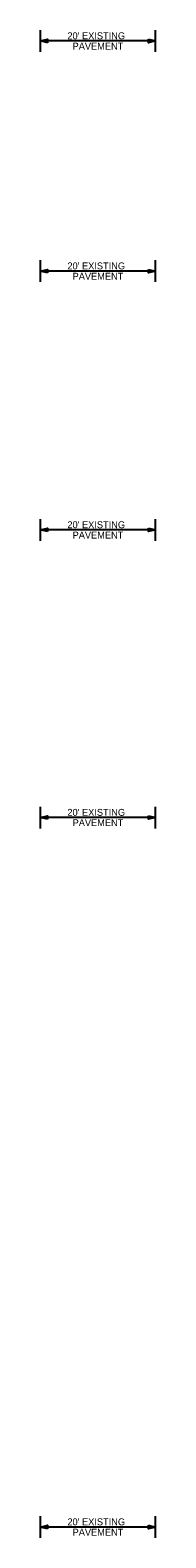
# Model space of a CAD drawing. Extents: x 1368713 to 1370673, y 380279 to 380950.
# Drawn here: x 1368712.9 to 1368732.9, y 380427.5 to 380689.6 of the extents above; entities that cross this region are included whole.
import ezdxf

# ---------------------------------------------------------------- set-up
doc = ezdxf.new("R2010")
doc.units = 0
doc.layers.add('R_ROW Annot', color=7, linetype='Continuous')

msp = doc.modelspace()

# ---------------------------------------------------------------- linework, layer by layer
at = {"layer": 'R_ROW Annot'}
for p, q in [((1368712.9, 380685.87), (1368712.9, 380689.64)), ((1368732.9, 380685.87), (1368732.9, 380689.64)), ((1368732.9, 380687.76), (1368712.9, 380687.76)), ((1368712.9, 380645.87), (1368712.9, 380649.64)), ((1368732.9, 380645.87), (1368732.9, 380649.64)), ((1368732.9, 380647.76), (1368712.9, 380647.76)), ((1368712.9, 380600.87), (1368712.9, 380604.64)), ((1368732.9, 380602.76), (1368712.9, 380602.76)), ((1368732.9, 380600.87), (1368732.9, 380604.64)), ((1368712.9, 380550.87), (1368712.9, 380554.64)), ((1368732.9, 380552.76), (1368712.9, 380552.76)), ((1368732.9, 380550.87), (1368732.9, 380554.64)), ((1368712.9, 380427.54), (1368712.9, 380431.3)), ((1368732.9, 380429.42), (1368712.9, 380429.42)), ((1368732.9, 380427.54), (1368732.9, 380431.3))]:
    msp.add_line(p, q, dxfattribs=at)
for points in [[(1368714.1, 380687.46), (1368712.9, 380687.76), (1368714.1, 380688.06)], [(1368731.7, 380688.06), (1368732.9, 380687.76), (1368731.7, 380687.46)], [(1368714.1, 380647.46), (1368712.9, 380647.76), (1368714.1, 380648.06)], [(1368731.7, 380648.06), (1368732.9, 380647.76), (1368731.7, 380647.46)], [(1368714.1, 380602.46), (1368712.9, 380602.76), (1368714.1, 380603.06)], [(1368731.7, 380603.06), (1368732.9, 380602.76), (1368731.7, 380602.46)], [(1368714.1, 380552.46), (1368712.9, 380552.76), (1368714.1, 380553.06)], [(1368731.7, 380553.06), (1368732.9, 380552.76), (1368731.7, 380552.46)], [(1368714.1, 380429.12), (1368712.9, 380429.42), (1368714.1, 380429.72)], [(1368731.7, 380429.72), (1368732.9, 380429.42), (1368731.7, 380429.12)]]:
    msp.add_lwpolyline(points, close=True, dxfattribs=at)

# ---------------------------------------------------------------- texts
for s, p in [("20' EXISTING", (1368717.58, 380688.06)), ('PAVEMENT', (1368718.48, 380686.26)), ("20' EXISTING", (1368717.58, 380648.06)), ('PAVEMENT', (1368718.48, 380646.26)), ("20' EXISTING", (1368717.58, 380603.06)), ('PAVEMENT', (1368718.48, 380601.26)), ("20' EXISTING", (1368717.58, 380553.06)), ('PAVEMENT', (1368718.48, 380551.26)), ("20' EXISTING", (1368717.58, 380429.72)), ('PAVEMENT', (1368718.48, 380427.92))]:
    msp.add_text(s, height=1.2, dxfattribs=at).set_placement(p)

doc.saveas('drawing.dxf')
